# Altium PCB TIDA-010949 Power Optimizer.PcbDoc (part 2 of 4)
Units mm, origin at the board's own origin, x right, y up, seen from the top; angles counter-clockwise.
Board outline 129.4 x 84 mm, 4 copper layers (Power1, Ground1, Ground2, Power2), stack 1.926 mm thick; 265 components, 128 nets, 802 pads, 1069 vias.
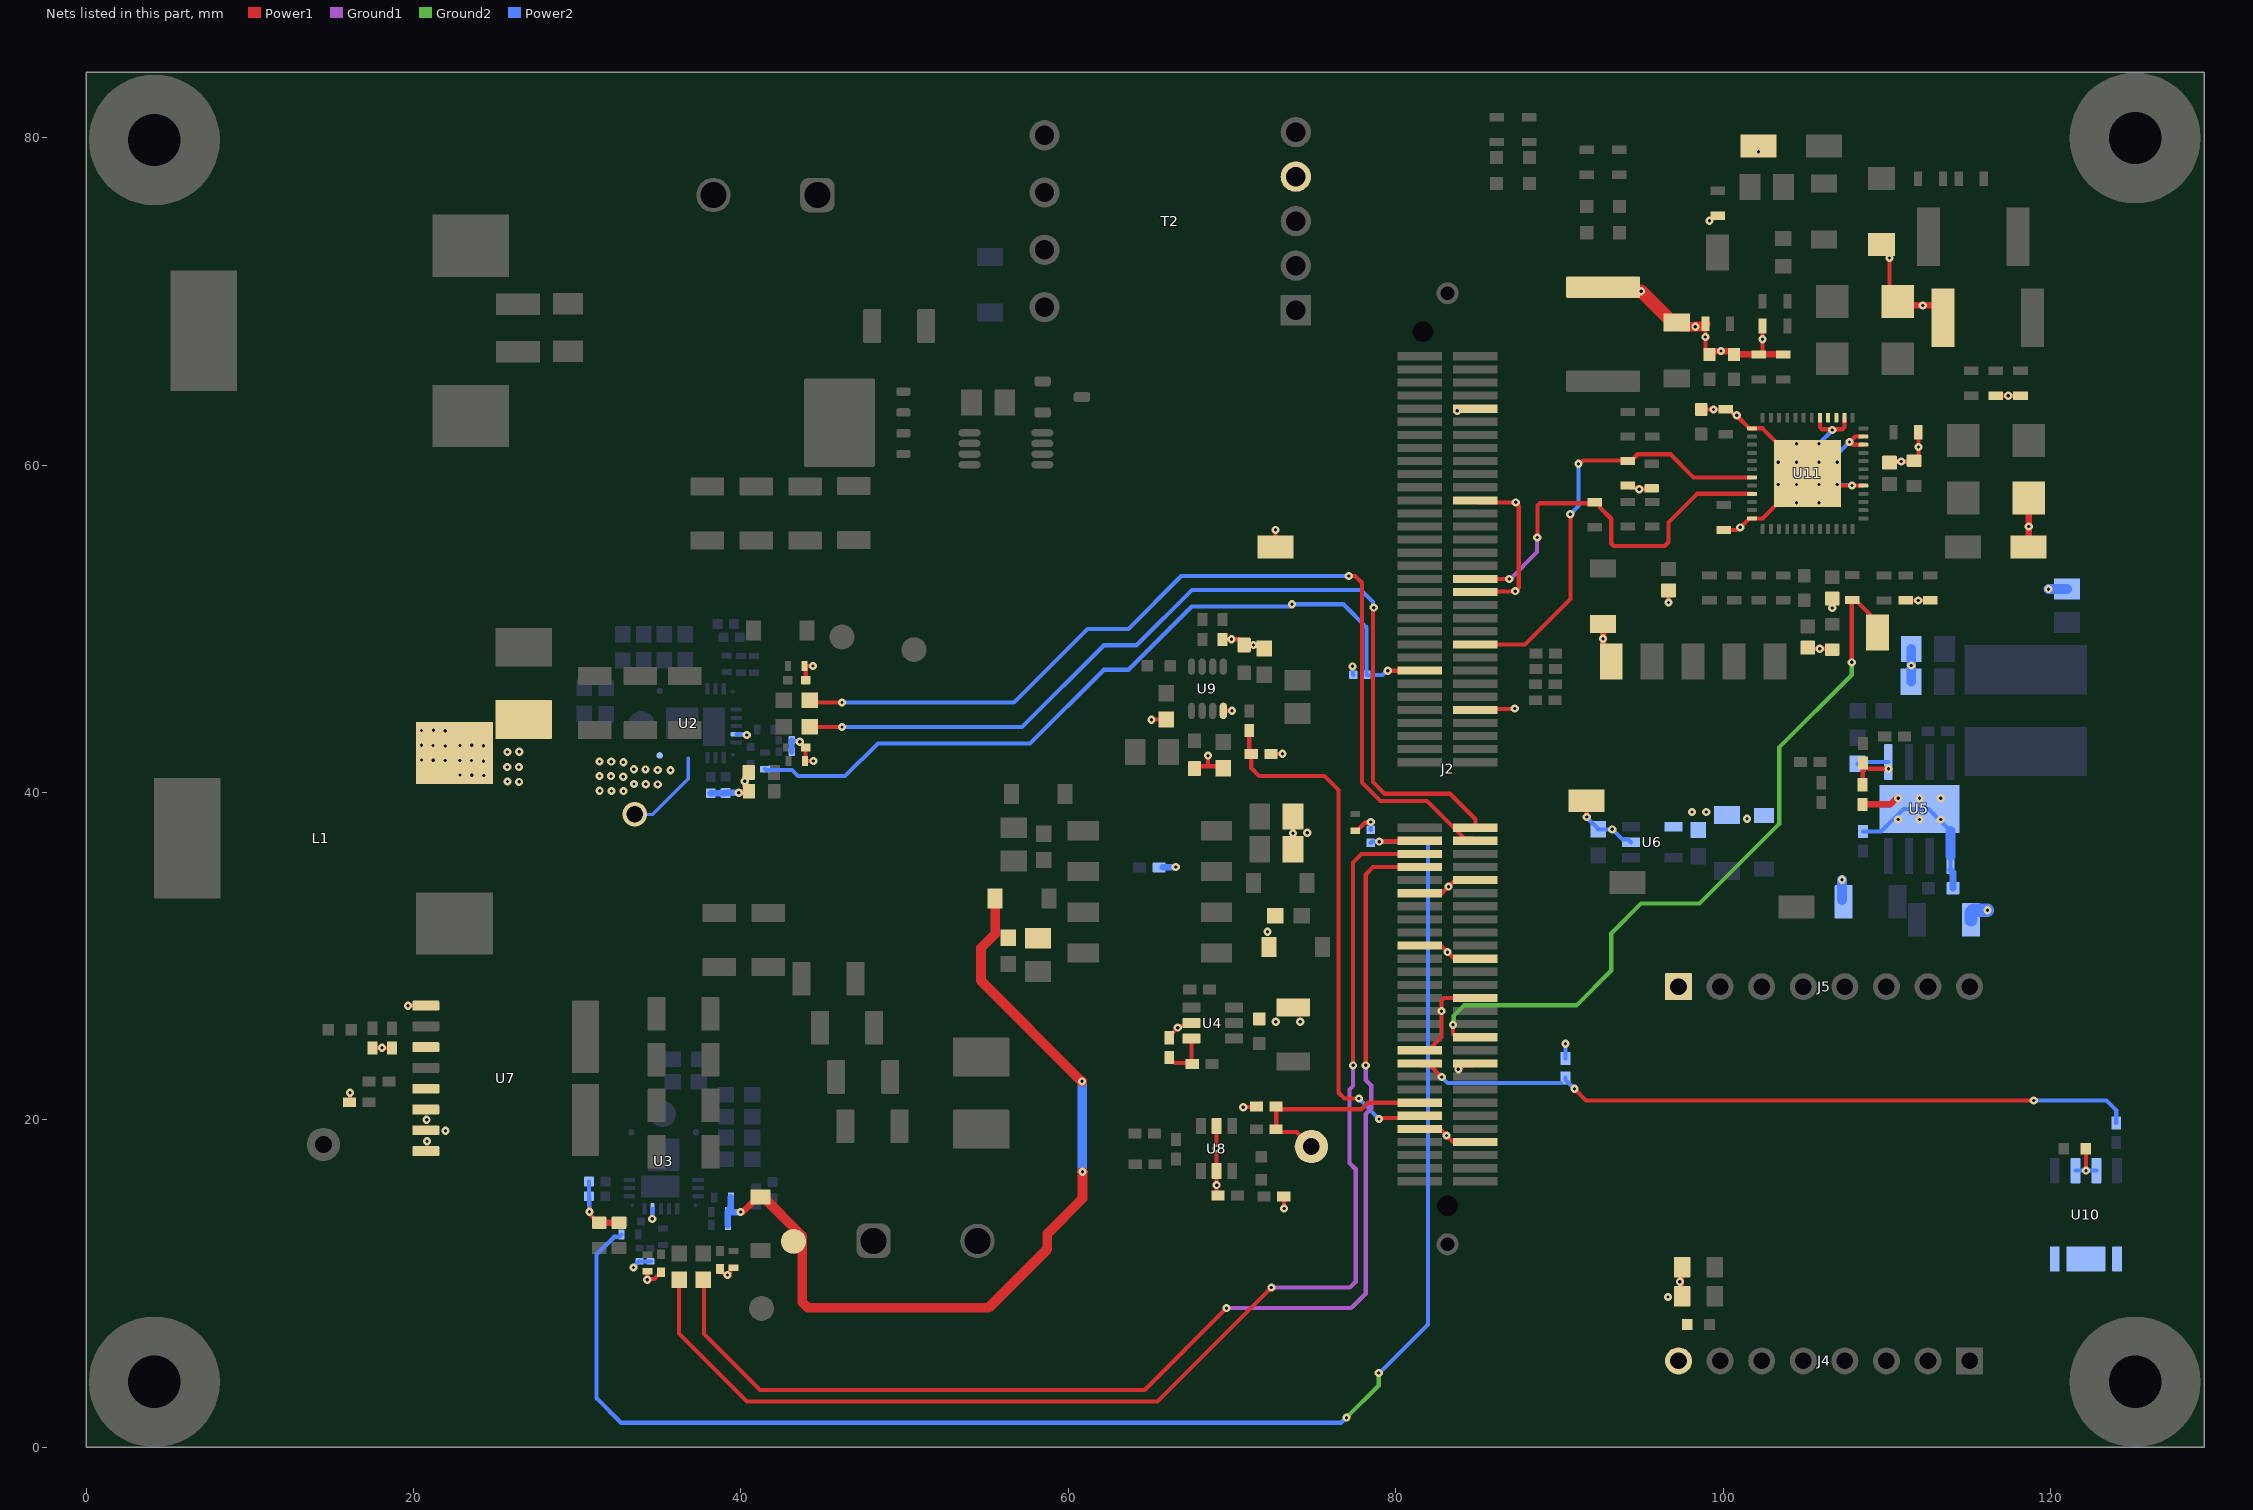
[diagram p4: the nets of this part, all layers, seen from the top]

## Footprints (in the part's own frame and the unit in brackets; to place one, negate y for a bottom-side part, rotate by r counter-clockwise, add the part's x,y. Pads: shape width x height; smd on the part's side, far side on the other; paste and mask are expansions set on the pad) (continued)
Wurth_750510476 [mm] "Wurth"
  rect 1.85x1.85 hole 1.181: 1(-8.175,5.44)
  round 1.85 hole 1.181: 2(-8.175,2.72) 3(-8.175,0) 4(-8.175,-2.72) 5(-8.175,-5.44) 6(7.175,-5.25) 7(7.175,-1.75) 8(7.175,1.75) 9(7.175,5.25)
  silkscreen extent -10.4,-6.9 9.9,6.9, body extent -9.88,-6.86 9.88,6.86, height 10.16

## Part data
C1: library part CMP-0007679-2, "CAP, CERM, 2.2 uF, 16 V, +/- 10%, X5R, 0805", Cap_Case=0805, Manufacturer=AVX, Supplier Part Number 1=478-2580-1-ND, TempCo=X5R, Tolerance_%=10%, Value1="0.009 ohm", Value2=16V, ValueDisplayed=2.2uF
C2 C3 C4 C21 C22 C23 C24 C25 C26 C27 C28 C29: library part CMP-0077894-3, "CAP, CERM, 0.22 µF, 100 V,+/- 10%, X7S, AEC-Q200 Grade 1, 0603", Cap_Case=0603, Manufacturer="Taiyo Yuden", Supplier Part Number 1=587-5012-1-ND, TempCo=X7S, Tolerance_%=10%, Value2=100V, ValueDisplayed=0.22µF
C5 C6 C7 C8 C9 C10 C11 C12 C13 C14 C15 C16 C17 C18 C19 C20 C47 C55 C56 C60 C61: library part CMP-0087970-1, "10µF ±10% 100V Ceramic Capacitor X7S 1210 (3225 Metric)", Manufacturer=Murata, TempCo=22%, Tolerance_%=0.1, ValueDisplayed=10uF
C30 C31 C65 C67: library part CMP-0006659-2, "CAP, CERM, 0.1 uF, 25 V, +/- 10%, X7R, 0402", Cap_Case=0402, Manufacturer=MuRata, Supplier Part Number 1=490-10698-1-ND, TempCo=X7R, Tolerance_%=10%, Value1=Unknown, Value2=25V, ValueDisplayed=0.1uF
C32 C33 C34 C35: library part CMP-0097874-1, "10 pF ±1% 50V Ceramic Capacitor C0G, NP0 0402 (1005 Metric)", Digikey Part Number=478-5717-1-ND, Manufacturer="KYOCERA AVX", Mouser Part Number=581-04025U100FAT2A, Operating Temperature Range="-55°C to +125°C", TempCo=30ppm/°C, Temperature Characteristic=C0G, Tolerance_%=1%, ValueDisplayed=10pF
C36 C37 C40 C41: library part CMP-0089452-2, "2.2µF ±10% 16V Ceramic Capacitor X7S 0603 (1608 Metric)", Digikey Part Number=490-12731-1-ND, Manufacturer=Murata, Mouser Part Number=81-GRM188C71C225KE1D, Operating Temperature Range="-55°C to +125°C", TempCo=22%, Temperature Characteristic=X7S, Tolerance_%=10%, ValueDisplayed=2.2uF
C38 C42: library part CMP-0096845-1, "Multi-Layer Ceramic Capacitor 100pF 25V C0G ±5% 0402 Paper T/R", Manufacturer=Murata, Operating Temperature Range="-55°C to +125°C", TempCo=30ppm/°C, Temperature Characteristic=C0G, Tolerance_%=5%, ValueDisplayed=100pF
C39 C43: library part CMP-0096975-1, "Multi-Layer Ceramic Capacitor 1uF 25V X5R ±10% 0402 Paper T/R", Manufacturer=Murata, Operating Temperature Range="-55°C to +85°C", TempCo=0.15, Temperature Characteristic=X5R, Tolerance_%=10%, ValueDisplayed=1uF
C44 C45 C50 C51 C113 C114 C115: library part CMP-0007677-2, "CAP, CERM, 10 uF, 16 V, +/- 10%, X5R, 0805", Cap_Case=0805, Manufacturer=AVX, Supplier Part Number 1=478-5165-1-ND, TempCo=X5R, Tolerance_%=10%, Value1=Unknown, Value2=16V, ValueDisplayed=10uF
C46: library part CMP-0006201-2, "CAP, CERM, 0.1 uF, 16 V, +/- 10%, X7R, 0402", Cap_Case=0402, Manufacturer=AVX, Supplier Part Number 1=478-7888-1-ND, TempCo=X7R, Tolerance_%=10%, Value1=Unknown, Value2=16V, ValueDisplayed=0.1uF
C48 C96 C97 C104 C111: library part CMP-0094779-1, "Cap Ceramic 100nF 100V X7R 10% SMD 0603 125°C Paper T/R", Digikey Part Number=478-06031C104K4T2ACT-ND, Manufacturer="KYOCERA AVX", Mouser Part Number=581-06031C104K4T2A, Operating Temperature Range="-55°C to +125°C", TempCo=15%, Temperature Characteristic=X7R, Tolerance_%=10%, ValueDisplayed=100nF
C49: library part CMP-0007254-4, "CAP, CERM, 200 pF, 100 V, +/- 5%, C0G/NP0, 0603", Cap_Case=0603, Manufacturer=MuRata, Supplier Part Number 1=490-1358-1-ND, TempCo=C0G/NP0, Tolerance_%=5%, Value1=Unknown, Value2=100V, ValueDisplayed=200pF
C52: library part CMP-0007475-4, "CAP, CERM, 2200 pF, 100 V, +/- 10%, X7R, 0603", Cap_Case=0603, Manufacturer=MuRata, Supplier Part Number 1=490-1478-1-ND, TempCo=X7R, Tolerance_%=10%, Value1=Unknown, Value2=100V, ValueDisplayed=2200pF
C53: library part CMP-0006683-2, "CAP, CERM, 2200 pF, 50 V, +/- 10%, X7R, 0402", Cap_Case=0402, Manufacturer=MuRata, Supplier Part Number 1=490-1305-1-ND, TempCo=X7R, Tolerance_%=10%, Value1=Unknown, Value2=50V, ValueDisplayed=2200pF
C54 C77: library part CMP-0006752-5, "CAP, CERM, 0.1 uF, 25 V, +/- 5%, X7R, 0603", Cap_Case=0603, Manufacturer=AVX, Supplier Part Number 1=478-3713-1-ND, TempCo=X7R, Tolerance_%=5%, Value1="0.05 ohm", Value2=25V, ValueDisplayed=0.1uF
C57 C58: library part CMP-0121608-1, "10 µF ±10% 16V Ceramic Capacitor X7R 0805 (2012 Metric)", Digikey Part Number=478-0805YC106KAT2ACT-ND, Manufacturer="Kyocera AVX", Mouser Part Number=581-0805YC106KAT2A, Operating Temperature Range="-55°C to +125°C", TempCo=15%, Temperature Characteristic=X7R, Tolerance_%=10%, ValueDisplayed=10uF
C59 C107: library part CMP-0090409-1, "0.1µF ±10% 16V Ceramic Capacitor X7R 0603 (1608 Metric)", Digikey Part Number=490-5796-1-ND, Manufacturer="Murata Electronics North America", Mouser Part Number=81-GCJ188R71C104KA1D, Operating Temperature Range="-55°C to +125°C", TempCo=15%, Temperature Characteristic=X7R, Tolerance_%=10%, ValueDisplayed=0.1uF
C62 C64: library part CMP-0006831-4, "CAP CER 1UF 16V Y5V 0603", Cap_Case=0603, Manufacturer=Yageo, PartNumber=CC0603MRY5V7BB105, Supplier Part Number 1=311-3414-1-ND, TempCo=X7R, Tolerance_%=10%, Value1=Unknown, Value2=16V, ValueDisplayed=1uF
C63: library part CMP-0008965-2, "CAP, CERM, 10 uF, 25 V, +/- 10%, X7R, 1206", Cap_Case=2220, Manufacturer=MuRata, Supplier Part Number 1=81-GRM31CR71E106KA12, TempCo=X7R, Tolerance_%=10%, Value1=Unknown, Value2=25V, ValueDisplayed=10uF
C66 C68: library part CMP-0078625-1, "CAP, CERM, 1 µF, 25 V,+/- 20%, X5R, 0402", Cap_Case=0402, Manufacturer=MuRata, Supplier Part Number 1=490-10018-1-ND, TempCo=X5R, Tolerance_%=20%, Value2=25V, ValueDisplayed=1µF
C69: library part CMP-0008996-2, "CAP, CERM, 0.39 uF, 100 V, +/- 10%, X7R, 1206", Cap_Case=1206, Manufacturer=MuRata, PartNumber=GRM31MR71H394KA01L, Supplier Part Number 1=490-1780-1-ND, TempCo=X7R, Tolerance_%=10%, Value1=Unknown, Value2=50V, ValueDisplayed=0.39uF
C70 C72: library part CMP-0006389-2, "CAP, CERM, 470 pF, 25 V, +/- 5%, C0G/NP0, 0402", Cap_Case=0402, Manufacturer=MuRata, Supplier Part Number 1=GRM1555C1E471JA01D-ND, TempCo=C0G/NP0, Tolerance_%=5%, Value1=Unknown, Value2=25V, ValueDisplayed=470pF
C71: library part CMP-0006658-2, "CAP, CERM, 0.01 uF, 25 V, +/- 10%, X7R, 0402", Cap_Case=0402, Manufacturer=MuRata, Supplier Part Number 1=490-1312-1-ND, TempCo=X7R, Tolerance_%=10%, Value1=Unknown, Value2=25V, ValueDisplayed=0.01uF
C73 C75: library part CMP-0860530-1, "CAP, CERM, 1000 pF, 25 V,+/- 5%, C0G/NP0, 0603", Cap_Case=0603, Manufacturer=Yageo, TempCo=C0G/NP0, Tolerance_%=5%, Value2=25V, ValueDisplayed=1000pF
C74 C76: library part CMP-0006453-2, "CAP, CERM, 300 pF, 50 V, +/- 5%, C0G/NP0, 0402", Cap_Case=0402, Manufacturer=MuRata, Supplier Part Number 1=490-3234-1-ND, TempCo=C0G/NP0, Tolerance_%=5%, Value1=Unknown, Value2=50V, ValueDisplayed=300pF
C78 C79: library part CMP-0006608-2, "CAP, CERM, 1 uF, 25 V, +/- 10%, X5R, 0402", Cap_Case=0402, Manufacturer=MuRata, Supplier Part Number 1=490-10017-1-ND, TempCo=X5R, Tolerance_%=10%, Value1=Unknown, Value2=25V, ValueDisplayed=1uF
C80 C83 C93 C95: library part CMP-0045719-1, "1000 pF ±10% 50V Ceramic Capacitor X7R 0603 (1608 Metric)", Digikey Part Number=399-C0603X102K5RAC7867CT-ND, Manufacturer=KEMET, Mouser Part Number=80-C0603X102K5R, Operating Temperature Range="-55°C to +125°C", TempCo=15%, Temperature Characteristic=X7R, Tolerance_%=10%, ValueDisplayed=1000pF
C81 C101 C106: library part CMP-0009015-2, "CAP, CERM, 10 uF, 50 V, +/- 10%, X5R, AEC-Q200 Grade 1, 1206", Cap_Case=1206, Manufacturer=MuRata, Supplier Part Number 1=490-12456-1-ND, TempCo=X5R, Tolerance_%=10%, Value1=Unknown, Value2=50V, ValueDisplayed=10uF
C82: library part CMP-0089171-1, "3300pF ±5% 100V Ceramic Capacitor X7R 0603 (1608 Metric)", Digikey Part Number=478-7420-1-ND, Manufacturer="AVX Corporation", Mouser Part Number=581-06031C332J4Z2A, Operating Temperature Range="-55°C to +125°C", TempCo=15%, Temperature Characteristic=X7R, Tolerance_%=5%, ValueDisplayed=3300pF
C84: library part CMP-0008779-2, "CAP, CERM, 1 uF, 100 V, +/- 10%, X7R, AEC-Q200 Grade 1, 1206", Cap_Case=1206_180, Manufacturer=TDK, Supplier Part Number 1=445-5845-1-ND, TempCo=X7R, Tolerance_%=10%, Value1="0.004575 ohm", Value2=100V, ValueDisplayed=1uF
C85: library part CMP-0007433-4, "CAP, CERM, 0.01 uF, 50 V, +/- 10%, X7R, 0603", Cap_Case=0603, Manufacturer=MuRata, Supplier Part Number 1=490-1512-1-ND, TempCo=X7R, Tolerance_%=10%, Value1=Unknown, Value2=50V, ValueDisplayed=0.01uF
C86 C99 C100 C102 C103 C105: library part CMP-0750039-1, "CAP, CERM, 0.01 µF, 50 V,+/- 10%, X7R, 0603", Cap_Case=0603, Manufacturer="Wurth Elektronik", TempCo=X7R, Tolerance_%=10%, Value2=50V, ValueDisplayed=0.01µF
C87: library part CMP-0007192-4, "CAP, CERM, 1800 pF, 50 V, +/- 5%, C0G/NP0, 0603", Cap_Case=0603, Manufacturer=MuRata, Supplier Part Number 1=490-1457-1-ND, TempCo=C0G/NP0, Tolerance_%=5%, Value1=Unknown, Value2=50V, ValueDisplayed=1800pF
C88: library part CMP-0006764-4, "CAP, CERM, 1000 pF, 50 V, +/- 10%, C0G/NP0, 0603", Cap_Case=0603, Manufacturer=AVX, Supplier Part Number 1=478-3718-1-ND, TempCo=C0G/NP0, Tolerance_%=10%, Value1="0.048 ohm", Value2=50V, ValueDisplayed=1000pF
C89: library part CMP-0007164-4, "CAP, CERM, 560 pF, 25 V, +/- 5%, C0G/NP0, 0603", Cap_Case=0603, Manufacturer=MuRata, Supplier Part Number 1=GRM1885C1E561JA01D-ND, TempCo=C0G/NP0, Tolerance_%=5%, Value1=Unknown, Value2=25V, ValueDisplayed=560pF
C90: library part CMP-0007203-4, "CAP, CERM, 270 pF, 50 V, +/- 5%, C0G/NP0, 0603", Cap_Case=0603, Manufacturer=MuRata, Supplier Part Number 1=490-1437-1-ND, TempCo=C0G/NP0, Tolerance_%=5%, Value1=Unknown, Value2=50V, ValueDisplayed=270pF
C91: library part CMP-0006729-4, "CAP, CERM, 1200 pF, 100 V, +/- 5%, X7R, 0603", Cap_Case=0603, Manufacturer=AVX, Supplier Part Number 1=478-3702-1-ND, TempCo=X7R, Tolerance_%=5%, Value1="0.254 ohm", Value2=100V, ValueDisplayed=1200pF
C92 C94: library part CMP-0122291-1, "1 µF ±10% 50V Ceramic Capacitor X7T 0603 (1608 Metric)", Digikey Part Number=490-GCM188D71H105KE36JCT-ND, Manufacturer=Murata, Mouser Part Number=81-GCM188D71H105KE6J, Operating Temperature Range="-55°C to +125°C", TempCo=+22/-33%, Temperature Characteristic=X7T, Tolerance_%=10%, ValueDisplayed=1uF
C98: library part CMP-0093976-1, "Cap Ceramic 47uF 25V X7R 20% Pad SMD 2220 +125°C Automotive T/R", Manufacturer=TDK, Operating Temperature Range="-55°C to +125°C", TempCo=0.15, Temperature Characteristic=X7R, Tolerance_%=0.2%, ValueDisplayed=47uF
C108: library part CMP-0006561-2, "CAP, CERM, 0.01 uF, 10 V, +/- 10%, X5R, 0402", Cap_Case=0402, Manufacturer=MuRata, Supplier Part Number 1=GRM155R61A103KA01D-ND, TempCo=X5R, Tolerance_%=10%, Value1=Unknown, Value2=10V, ValueDisplayed=0.01uF
C109 C110: library part CMP-0098338-1, "100 pF ±5% 16V Ceramic Capacitor C0G, NP0 0402 (1005 Metric)", Digikey Part Number=399-C0402C101J4GAC7867CT-ND, Manufacturer=KEMET, Mouser Part Number=80-C0402C101J4G, Operating Temperature Range="-55°C to +125°C", TempCo=30ppm/°C, Temperature Characteristic=C0G, Tolerance_%=5%, ValueDisplayed=100pF
C112: library part CMP-0006640-2, "CAP, CERM, 0.1 uF, 16 V, +/- 5%, X7R, 0402", Cap_Case=0402, Manufacturer=MuRata, Supplier Part Number 1=490-6327-1-ND, TempCo=X7R, Tolerance_%=5%, Value1=Unknown, Value2=16V, ValueDisplayed=0.1uF
D1 D4 D5: library part CMP-0028543-2, "Diode, Schottky, 40 V, 0.35 A, SOD-123", Manufacturer="Diodes Inc.", Value1=0.35A, Value2=0.55V
D2 D3 D6: library part CMP-0077599-3, "Diode, Zener, 5.1 V, 500 mW, SOD-123", Manufacturer=Vishay-Semiconductor, Power_W=500mW, Value1=0.5W
D7 D15: library part CMP-0002946-3, "LED, Blue, SMD", Color=Blue, Manufacturer="Wurth Elektronik", Power_TotalModule=105mW, Value1=0.105W, Value2=3.2V
D8: library part CMP-0005782-1, "Diode, Zener, 3.6 V, 500 mW, SOD-123", Manufacturer="ON Semiconductor", PartNumber=MMSZ4685T1G, Power_W=500mW, Supplier Part Number 1=MMSZ4685T1GOSCT-ND, Value1=0.5W
D9 D11 D13 D14: library part CMP-0028416-2, "Diode, Schottky, 50 V, 3 A, SMA", Manufacturer="Diodes Inc.", Value1=3A, Value2=0.7V
D10: library part CMP-0085011-1, "Diode, TVS, Bi, 22 V, 35.5 Vc, 400 W, 11.3 A, SMA (non-polarized)", Manufacturer=Littelfuse, Value1=35.5V
D12 D16: library part CMP-0002947-3, "LED, Red, SMD", Color=Red, Manufacturer="Wurth Elektronik", Power_TotalModule=72mW, Value1=0.072W, Value2=2V
FB1 FB2 FB3: library part CMP-0037505-1, "600 Ohms @ 100 MHz 1 Power, Signal Line Ferrite Bead 0603 (1608 Metric) 1A 200mOhm", Digikey Part Number=MH1608-601YCT-ND, Impedance At Frequency="600Ω @ 100MHz", Manufacturer=Bourns, Mouser Part Number=652-MH1608-601Y, Operating Temperature Range="-55°C to +125°C", Test Frequency=100MHz, Tolerance_%=25%
H1 H2 H3 H4: library part CMP-0003617-1, "Machine Screw, Round, #4-40 x 1/4, Nylon, Philips panhead", Manufacturer="B&F Fastener Supply", Supplier Part Number 1=H542-ND
H5 H6 H7 H8: library part CMP-0003610-1, "Standoff, Hex, 0.5\"L #4-40 Nylon", Manufacturer=Keystone, Supplier Part Number 1=36-1902C-ND
J1 J3: library part CMP-0075360-1, "Terminal Block, 6.35mm, 2x1, TH", Color=Green, Current_A=30A, Manufacturer="On-Shore Technology", Supplier Part Number 1=ED2675-ND, Voltage_V=300V
J2: library part CMP-0003814-2, "C2000 controlCARD-120HSEC connector, SMT", Manufacturer=Samtec
J4 J5: library part CMP-0075419-2, "Header, 100mil, 8x1, Gold, TH", Color=Black, Current_A=6.3A, Manufacturer=Samtec, Supplier Part Number 1=SAM1029-08-ND, Voltage_V=550V
L1 L4: library part CMP-0060824-1, "Inductor, Shielded E Core, Ferrite, 3.6 uH, 25 A, 0.0017 ohm, SMD", Manufacturer=Coilcraft, Value1="0.0017 ohm", Value2=25A, ValueDisplayed=3.6uH
L2: library part CMP-0102060-1, "WE-PD2SA SMT Power Inductor, size 7850, 68uH, 1.12A, 290mOhm", Case/Size Code=7850, DC Resistance=246mOhm, DC Resistance Max=290mOhm, Inductance=68uH, Manufacturer="Wurth Elektronik", Operating Temperature Max=150°C, Operating Temperature Min=-50°C, Rated Current=1.12A, Saturation Current=1A, Self Resonant Frequency=7.5MHz
L3: library part CMP-0058657-1, "Inductor, Wirewound, Ferrite, 1 uH, 0.595 A, 0.25 ohm, SMD", Manufacturer=MuRata, Value1="0.25 ohm", Value2=0.595A, ValueDisplayed=1uH
L5: library part CMP-0061680-2, "Inductor, Drum Core, Ferrite, 1 mH, 0.1 A, 19 ohm, SMD", Manufacturer=Coilcraft, Value1="19 ohm", Value2=0.1A, ValueDisplayed=1mH
L6: library part CMP-0061972-2, "Inductor, Drum Core, Ferrite, 1.5 mH, 0.08 A, 21 ohm, SMD", Manufacturer=Coilcraft, Value1="21 ohm", Value2=0.08A, ValueDisplayed=1.5mH
LBL1: library part CMP-0003625-1, "Thermal Transfer Printable Labels, 0.650\" W x 0.200\" H - 10,000 per roll", Manufacturer=Brady, Supplier Part Number 1=97C5133
Logo1: library part CMP-0074838-1, "Texas Instrument Corporate Signature"
Logo2: library part CMP-0074844-1
Logo3: library part CMP-0074847-1, "FCC_disclaimer"
Logo4: library part CMP-0074769-1
Q1: library part CMP-0000958-3, "MOSFET, N-CH, 100 V, 17 A, DNK0008A (VSON-CLIP-8)", Alternate Manufacturer=None, Manufacturer="Texas Instruments", Supplier Part Number 1=296-37478-6-ND, Value2="48 nC"
Q2: library part CMP-0000949-3, "MOSFET, N-CH, Depletion Mode, 100 V, 0.17 A, AEC-Q101, SOT-23", Alternate Manufacturer=None, Manufacturer="Infineon Technologies", Supplier Part Number 1="BSS169 H6327-ND", Value2="2.1 nC"
R1: library part CMP-0094948-1, "0 Ohms Jumper 0.1W, 1/10W Chip Resistor 0402 (1005 Metric) - Thick Film", Digikey Part Number=2679-CR0402-10W-000TTR-ND, Manufacturer=Venkel, Operating Temperature Range="-55°C to +155°C", Power_W=100mW
R2 R6: library part CMP-0042666-1, "Res Metal Strip 2512 0.001 Ohm 1% 3W ±50ppm/C Pad SMD Automotive T/R", Manufacturer="TT Electronics", Mouser Part Number=66-ULRG3R001FLFSLT, Operating Temperature Range=to, Power_W=3W, TempCo=50ppm/°C, Tolerance_%=1%
R3 R4 R5 R7: library part CMP-0026262-2, "RES, 2.00, 1%, 0.063 W, AEC-Q200 Grade 0, 0402", Manufacturer=Vishay-Dale, Power_W=63mW, Supplier Part Number 1=541-2.00LLCT-ND, TempCo="100 ppm/C", Tolerance_%=1%, Value2=0.063W, Value_Code=2R00, ValueDisplayed=2.00
R8 R9 R14 R15: library part CMP-0078781-1, "RES, 10.5 k, 1%, 0.063 W, 0402", Manufacturer="Yageo America", Power_W=63mW, Supplier Part Number 1=YAG2951CT-ND, TempCo="100 ppm/C", Tolerance_%=1%, Value2=0.063W, Value_Code=10k5, ValueDisplayed=10.5k
R10 R11 R12 R13: library part CMP-0022908-4, "RES, 20.0, 1%, 0.1 W, 0603", Manufacturer=Yageo, Power_W=100mW, Supplier Part Number 1=311-20.0HRCT-ND, TempCo="100 ppm/C", Tolerance_%=1%, Value2=0.1W, Value_Code=20R0, ValueDisplayed=20.0
R16 R17 R58: library part CMP-0022895-5, "RES, 1.00 k, 1%, 0.1 W, 0603", Manufacturer=Yageo, Power_W=100mW, Supplier Part Number 1=311-1.00KHRCT-ND, TempCo="100 ppm/C", Tolerance_%=1%, Value2=0.1W, Value_Code=1k00, ValueDisplayed=1.00k
R18: library part CMP-0026325-2, "RES, 392 k, 1%, 0.063 W, AEC-Q200 Grade 0, 0402", Manufacturer=Vishay-Dale, Power_W=63mW, Supplier Part Number 1=541-392KLCT-ND, TempCo="100 ppm/C", Tolerance_%=1%, Value2=0.063W, Value_Code=392k
R19 R24 R26 R27 R28 R73 R75: library part CMP-0026936-3, "RES, 47, 5%, 0.063 W, AEC-Q200 Grade 0, 0402", Manufacturer=Vishay-Dale, Power_W=63mW, Supplier Part Number 1=541-47JCT-ND, TempCo="200 ppm/C", Tolerance_%=5%, Value2=0.063W, Value_Code=47R0, ValueDisplayed=47
R20: library part CMP-0026457-2, "RES, 57.6 k, 1%, 0.063 W, AEC-Q200 Grade 0, 0402", Manufacturer=Vishay-Dale, Power_W=63mW, Supplier Part Number 1=541-57.6KLCT-ND, TempCo="100 ppm/C", Tolerance_%=1%, Value2=0.063W, Value_Code=57k6, ValueDisplayed=57.6k
R21: library part CMP-0025971-3, "RES, 115 k, 1%, 0.063 W, AEC-Q200 Grade 0, 0402", Manufacturer=Vishay-Dale, Power_W=63mW, Supplier Part Number 1=541-115KLCT-ND, TempCo="100 ppm/C", Tolerance_%=1%, Value2=0.063W, Value_Code=115k
R22: library part CMP-0026825-5, "RES, 10 k, 5%, 0.063 W, AEC-Q200 Grade 0, 0402", Manufacturer=Vishay-Dale, Power_W=63mW, Supplier Part Number 1=541-10KJCT-ND, TempCo="200 ppm/C", Tolerance_%=5%, Value2=0.063W, Value_Code=10k0, ValueDisplayed=10k
R23: library part CMP-0083579-1, "RES, 5.6, 5%, 0.5 W, 1210", Manufacturer=Yageo, Power_W=500mW, TempCo="200 ppm/C", Tolerance_%=5%, Value2=0.5W, Value_Code=5R60, ValueDisplayed=5.6
R25: library part CMP-0025958-3, "RES, 10.0 k, 1%, 0.063 W, AEC-Q200 Grade 0, 0402", Manufacturer=Vishay-Dale, Power_W=63mW, Supplier Part Number 1=541-10.0KLCT-ND, TempCo="100 ppm/C", Tolerance_%=1%, Value2=0.063W, Value_Code=10k0, ValueDisplayed=10.0k
R29 R61 R62 R76: library part CMP-0025936-5, "RES, 680, 5%, 0.1 W, 0603", Manufacturer=Yageo, Power_W=100mW, Supplier Part Number 1=311-680GRCT-ND, TempCo="100 ppm/C", Tolerance_%=5%, Value2=0.1W, Value_Code=680R, ValueDisplayed=680
R30 R38: library part CMP-0025923-5, "RES, 43 k, 5%, 0.1 W, 0603", Manufacturer=Yageo, Power_W=100mW, Supplier Part Number 1=311-43KGRCT-ND, TempCo="100 ppm/C", Tolerance_%=5%, Value2=0.1W, Value_Code=43k0, ValueDisplayed=43k
R31 R32 R63: library part CMP-0026751-1, "RES, 47.0, 1%, 0.063 W, 0402", Manufacturer="KOA Speer", Power_W=63mW, Supplier Part Number 1=660-RK73H1ETTP47R0F, TempCo="100 ppm/C", Tolerance_%=1%, Value2=0.063W, Value_Code=47R0, ValueDisplayed=47.0
R33: library part CMP-0026486-2, "RES, 60.4 k, 1%, 0.063 W, AEC-Q200 Grade 0, 0402", Manufacturer=Vishay-Dale, Power_W=63mW, Supplier Part Number 1=541-60.4KLCT-ND, TempCo="100 ppm/C", Tolerance_%=1%, Value2=0.063W, Value_Code=60k4, ValueDisplayed=60.4k
R34 R37: library part CMP-0026749-1, "RES, 10.0, 1%, 0.063 W, 0402", Manufacturer="KOA Speer", Power_W=63mW, Supplier Part Number 1=660-RK73H1ETTP10R0F, TempCo="100 ppm/C", Tolerance_%=1%, Value2=0.063W, Value_Code=10R0, ValueDisplayed=10.0
R35: library part CMP-0025993-3, "RES, 12.7 k, 1%, 0.063 W, AEC-Q200 Grade 0, 0402", Manufacturer=Vishay-Dale, Power_W=63mW, Supplier Part Number 1=541-12.7KLCT-ND, TempCo="100 ppm/C", Tolerance_%=1%, Value2=0.063W, Value_Code=12k7, ValueDisplayed=12.7k
R39 R51: library part CMP-0025928-5, "RES, 510, 5%, 0.1 W, 0603", Manufacturer=Yageo, Power_W=100mW, Supplier Part Number 1=311-510GRCT-ND, TempCo="100 ppm/C", Tolerance_%=5%, Value2=0.1W, Value_Code=510R, ValueDisplayed=510
R40 R41: library part CMP-0019234-2, "RES, 30.1 k, 0.5%, 0.1 W, 0805", Manufacturer="Susumu Co Ltd", Power_W=100mW, Supplier Part Number 1=RR12P30.1KDCT-ND, TempCo="25 ppm/C", Tolerance_%=0.5%, Value2=0.1W, Value_Code=30k1, ValueDisplayed=30.1k
R42 R44: library part CMP-0026454-2, "RES, 56.2, 1%, 0.063 W, AEC-Q200 Grade 0, 0402", Manufacturer=Vishay-Dale, Power_W=63mW, Supplier Part Number 1=541-56.2LCT-ND, TempCo="100 ppm/C", Tolerance_%=1%, Value2=0.063W, Value_Code=56R2, ValueDisplayed=56.2
R43 R45: library part CMP-0088560-2, "High Precision-High Stability Chip Resistor Thin Film 0603 1kOhm 0.1% Paper T/R", Digikey Part Number=YAG1237CT-ND, Manufacturer=Yageo, Mouser Part Number=603-RT0603BRD071KL, Operating Temperature Range="-55°C to +155°C", Power_W=100mW, TempCo=25ppm/°C, Tolerance_%=0.1%
R46 R47 R48 R49 R53 R54 R60: library part CMP-0098286-1, "10 kOhms ±5% 0.1W, 1/10W Chip Resistor 0603 (1608 Metric) Thick Film", Digikey Part Number=541-CRCW060310K0JNEBCCT-ND, Manufacturer=Vishay, Mouser Part Number=71-CRCW060310K0JNEBC, Operating Temperature Range="-55°C to +155°C", Power_W=100mW, TempCo=200ppm/°C, Tolerance_%=5%
R50 R52: library part CMP-0022735-5, "RES, 100 k, 1%, 0.1 W, 0603", Manufacturer=Yageo, Power_W=100mW, Supplier Part Number 1=311-100KHRCT-ND, TempCo="100 ppm/C", Tolerance_%=1%, Value2=0.1W, Value_Code=100k
R55: library part CMP-0025913-5, "RES, 33 k, 5%, 0.1 W, 0603", Manufacturer=Yageo, Power_W=100mW, Supplier Part Number 1=311-33KGRCT-ND, TempCo="100 ppm/C", Tolerance_%=5%, Value2=0.1W, Value_Code=33k0, ValueDisplayed=33k
R56: library part CMP-0020737-3, "RES, 4.7, 5%, 0.125 W, AEC-Q200 Grade 0, 0805", Manufacturer=Panasonic, Power_W=125mW, Supplier Part Number 1=P4.7ACT-ND, TempCo="600 ppm/C", Tolerance_%=5%, Value2=0.125W, Value_Code=4R70, ValueDisplayed=4.7
R57: library part CMP-0025912-5, "RES, 330, 5%, 0.1 W, 0603", Manufacturer=Yageo, Power_W=100mW, Supplier Part Number 1=311-330GRCT-ND, TempCo="100 ppm/C", Tolerance_%=5%, Value2=0.1W, Value_Code=330R, ValueDisplayed=330
R59: library part CMP-0022986-5, "RES, 2.20 k, 1%, 0.1 W, 0603", Manufacturer=Yageo, Power_W=100mW, Supplier Part Number 1=311-2.20KHRCT-ND, TempCo="100 ppm/C", Tolerance_%=1%, Value2=0.1W, Value_Code=2k20, ValueDisplayed=2.20k
R64 R65 R66 R67 R68 R69 R70 R71: library part CMP-0031873-1, "0 Ohms Jumper Chip Resistor 0402 (1005 Metric) Anti-Sulfur, Current Sense, Flame Retardant Coating, Moisture Resistant, Safety Metal Foil", Digikey Part Number=4463-D1LPC0402CJUMPF-T10CT-ND, Manufacturer="Thin Film Technology", Max Current=20A, Operating Temperature Range="-55°C to +170°C"
R72 R74: library part CMP-0094624-1, "4.7 kOhms ±5% 0.1W, 1/10W Chip Resistor 0402 (1005 Metric) Automotive AEC-Q200 Thick Film", Digikey Part Number=10-ERJ-H2GJ472XCT-ND, Manufacturer=Panasonic, Mouser Part Number=667-ERJ-H2GJ472X, Operating Temperature Range="-55°C to +175°C", Power_W=100mW, TempCo=200ppm/°C, Tolerance_%=5%
T1: library part "EP7, 070-7148", "EP7 8-Term., SMT, Horizontal", Manufacturer="Würth Elektronik Midcom", Package=EP7
T2: library part CMP-0030703-1, "Transformer, 870uH. TH", Manufacturer="Wurth Elektronik", ValueDisplayed=870uH
TP1 TP13 TP14 TP15 TP18 TP19 TP20 TP21 TP22 TP23 TP24 TP25 TP26 TP27 TP28: library part CMP-0003968-1, "Test Point, SMT", Manufacturer=Harwin, Supplier Part Number 1=952-2664-1-ND
TP16 TP17: library part CMP-0055138-2, "Test Point, Miniature, Black, TH", Color=Black, Manufacturer="Keystone Electronics", Supplier Part Number 1=36-5001-ND
U1: library part CMP-0076397-2, "Zero Iq Reverse Polarity Protection Smart Diode Controller, DGK0008A (VSSOP-8)", Alternate Manufacturer="Texas Instruments"
U2 U3: library part CMP-0120692-1, "100-V, 53-A GaN Half-Bridge Power Stage", Manufacturer="Texas Instruments", Max Supply Voltage=5.25V, Min Supply Voltage=4.75V, Nominal Supply Current=12mA, Operating Temperature Range="-40°C to +125°C"
U4: library part CMP-0121876-1, "SIMPLE SWITCHER® Power Converter, 4-V to 42-V, 1-A Buck Converter, SOT23", Manufacturer="Texas Instruments", Max Supply Voltage=42V, Min Supply Voltage=4V, Nominal Supply Current=26.5-420uA, Operating Temperature Range="-40°C to +150°C", Output Voltage=0.8-28V, Switching Frequency=400kHz
U5: library part CMP-0089262-2, "Buck Switching Regulator IC Positive Adjustable 1.2V 1 Output 1A 8-PowerSOIC (0.154\", 3.90mm Width)", Digikey Part Number=296-LM5164DDARCT-ND, Manufacturer="Texas Instruments", Max Supply Voltage=100V, Min Supply Voltage=6V, Mouser Part Number=595-LM5164DDAR, Nominal Supply Current=600uA, Operating Temperature Range="-40°C to +150°C", Output Voltage=1.2-90V, Switching Frequency=1MHz
U6: library part CMP-0092532-1, "300-mA, Ultra-Low-Noise, Low-IQ, High PSRR LDO", Digikey Part Number=296-TPS7A2033PDBVRCT-ND, Dropout Voltage=145mV, Manufacturer="Texas Instruments", Max Supply Voltage=6V, Min Supply Voltage=1.6V, Mouser Part Number=595-TPS7A2033PDBVR, Nominal Supply Current=6.5uA, Operating Temperature Range="-40°C to +125°C", Output Voltage=3.3V
U7: library part CMP-0097970-1, Manufacturer="Texas Instruments", Operating Temperature Range=to
U8: library part CMP-0013234-2, "Bidirectional, Low- and High-Side Measurement, Multichannel, Voltage Output, Current-Sense Amplifier, DBV0006A (SOT-6)", Alternate Manufacturer="Texas Instruments"
U9: library part CMP-0086102-1, "TLV9002IDDFR, DDF0008A (SOT-23-THN-8)", Alternate Manufacturer="Texas Instruments"
U10: library part CMP-0122473-1, "Automotive ±1.5°C, 3-kVRMS Isolated Temperature Sensor With Analog Output With < 2 Seconds Response Time and 500VRMS Working Voltage", Manufacturer="Texas Instruments", Max Supply Voltage=5.5V, Min Supply Voltage=2.3V, Operating Supply Current=10uA, Operating Temperature Range="-40°C to +150°C"
U11: library part CMP-0040436-2, "Powerline Communications Analog Front End, 7 to 26 V, -40 to 125 degC, 48-pin QFN (RGZ48), Green (RoHS & no Sb/Br)", Manufacturer="Texas Instruments", Rating=Catalog, Total Supply Voltage(Max)(+5V is 5, +/-5V is 10)=26, Total Supply Voltage(Min)(+5V is 5, +/-5V is 10)=7

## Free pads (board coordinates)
  round 1.524 smd: 2(43.213,12.58) 3(41.267,8.486) 4(46.174,49.5) 5(50.58,48.73)

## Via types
v1: diameter 0.5, hole 0.2, Power1 to Power2, tented both sides, 1061 vias
v2: diameter 1.5/1.5/1.5/1.5 (per signal layer), hole 1, Power1 to Power2, 4 vias
v3: diameter 3.508, hole 3.1, Power1 to Power2, tented both sides, 4 vias

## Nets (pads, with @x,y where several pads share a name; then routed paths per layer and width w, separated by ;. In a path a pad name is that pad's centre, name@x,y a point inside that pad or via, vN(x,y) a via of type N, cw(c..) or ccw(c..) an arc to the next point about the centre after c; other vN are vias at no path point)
5V_FB: R20.1 R25.2 U4.3 | length 3.1
  Power1 w0.254: R25.2@66.174,23.818 66.174,23.718 66.347,23.545 66.447,23.545 66.524,23.468 67.524,23.468 U4.3@67.524,24.968
ADCIN: J2.23 R57.2 TP27.1 | length 46.6
  Power1 w0.254: v1(83.506,25.813) 83.506,25.267 83.723,25.05 J2.23@84.874,25.05 ; v1(107.864,47.953) 107.864,51.731 R57.2@107.9,51.767 108.091,51.767 TP27.1@109.674,50.184
  Ground2 w0.254: v1(83.506,25.813) 83.555,25.862 83.555,26.381 84.174,27 91.055,27 93.174,29.119 93.174,31.395 94.989,33.211 98.564,33.211 103.432,38.079 103.432,42.759 107.864,47.19 v1(107.864,47.953)
amb_tmp: U10.5 U10.6 U10.7
amb_tmp_mcu: C108.1 J2.20 R63.1 | length 44.5
  Power1 w0.254: J2.20@81.474,23.45 81.597,23.327 82.115,23.327 v1(82.814,22.627) ; v1@90.894,21.931 v1(90.924,21.902) 91.634,21.192 v1(118.982,21.192)
  Power2 w0.254: v1(82.814,22.627) 83.181,22.261 C108.1@90.084,22.261 ; C108.1@90.374,22.6 C108.1@90.374,22.55 90.374,22.45 90.922,21.902 v1(90.924,21.902) ; v1(118.982,21.192) 123.437,21.192 124.02,20.609 R63.1@124.02,19.811
BOOST_FLT: C109.2 J2.72 R73.1 | length 48.1
  Power1 w0.254: v1(79.514,47.443) 81.466,47.443 J2.72@81.474,47.45
  Power2 w0.254: R73.1@41.474,41.427 41.532,41.368 43.122,41.368 43.49,41 46.37,41 48.37,43 57.674,43 62.174,47.5 63.674,47.5 67.546,51.373 73.546,51.373 v1(73.674,51.5) 76.812,51.5 78.219,50.093 C109.2@78.219,47.188 79.191,47.188 79.446,47.443 v1(79.514,47.443)
BOOST_HI_PWM: J2.53 R10.1 | length 57.8
  Power1 w0.254: R10.1@44.215,45.635 44.35,45.5 v1(46.174,45.5) ; v1(77.136,53.229) 77.53,53.229 77.941,52.817 77.941,40.611 79.065,39.487 81.921,39.487 84.235,37.173 84.751,37.173 J2.53@84.874,37.05
  Power2 w0.254: v1(46.174,45.5) 56.674,45.5 61.174,50 63.674,50 66.902,53.229 v1(77.136,53.229)
BOOST_LO_PWM: J2.55 R12.1 | length 56.9
  Power1 w0.254: R12.1@44.215,44.01 44.225,44 v1(46.174,44) ; v1(78.662,51.295) 78.618,51.252 78.618,40.641 79.332,39.928 83.311,39.928 84.874,38.365 J2.55@84.874,37.85
  Power2 w0.254: v1(46.174,44) 57.174,44 62.174,49 64.174,49 67.551,52.377 77.868,52.377 78.614,51.631 78.614,51.342 v1(78.662,51.295)
BOOST_SW: L1.2 R6.2 U2.5 | length 5.5
  Power2 w0.2: v2(33.512,38.662) 34.621,38.662 36.793,40.834 36.793,42.11
  other v1: 32.823,40.086 31.371,40.111 32.09,40.094 34.194,40.508 34.927,40.5 33.475,40.524 25.736,40.667 26.455,40.651 32.816,40.963 32.072,41.001 31.359,41.006 23.558,41.05 24.291,41.041 22.839,41.066 34.919,41.376 35.697,41.359 33.463,41.42 34.175,41.415 26.437,41.557 25.724,41.562 32.823,41.85 32.079,41.888 31.366,41.893 24.284,41.918 21.947,41.961 22.827,41.961 23.54,41.956 20.495,41.985 21.214,41.969 25.734,42.476 26.457,42.486 21.94,42.837 20.483,42.881 21.196,42.876 22.837,42.875 24.281,42.861 23.56,42.885 20.493,43.794 21.937,43.78 21.216,43.804
BUCK_FLT: C110.2 J2.54 R75.1 | length 100.6
  Power1 w0.254: v1(79,37) 79.025,37.025 81.449,37.025 J2.54@81.474,37.05
  Ground2 w0.254: v1(76.997,1.812) 78.968,3.783 v1(78.968,4.539)
  Power2 w0.254: R75.1@32.712,12.999 32.575,12.862 32.268,12.862 31.174,11.768 31.174,3 32.674,1.5 76.666,1.5 v1@76.997,1.83 ; C110.2@78.476,36.918 78.557,37 v1(79,37) 81.83,37 81.979,36.851 81.979,7.502 79.017,4.539 v1(78.968,4.539)
BUCK_HI_PWM: J2.50 R11.1 | length 77
  Power1 w0.254: R11.1@37.7,10.239 37.756,10.183 37.756,6.917 41.174,3.5 64.674,3.5 v1(69.674,8.5) ; v1(78.176,23.331) 78.174,23.334 78.174,35 78.623,35.45 J2.50@81.474,35.45
  Ground1 w0.254: v1(69.674,8.5) 77.29,8.5 78.174,9.383 78.174,20.364 78.509,20.699 78.509,22.106 78.176,22.439 v1(78.176,23.331)
BUCK_LO_PWM: J2.52 R13.1 | length 79.5
  Power1 w0.254: R13.1@36.225,10.239 36.225,6.948 40.382,2.792 65.443,2.792 v1(72.409,9.758) ; v1(77.406,23.331) 77.406,35.732 77.923,36.25 J2.52@81.474,36.25
  Ground1 w0.254: v1(72.409,9.758) 77.202,9.758 77.561,10.117 77.561,16.983 77.174,17.371 77.174,21.85 77.406,22.082 v1(77.406,23.331)
DAC_EN: J2.75 R53.2 U11.7 | length 26.5
  Power1 w0.254: J2.75@84.874,49.05 87.898,49.05 90.674,51.826 v1(90.674,57) ; v1(91.174,60.086) 91.242,60.086 91.447,60.291 94.132,60.291 R53.2@94.174,60.25 ; R53.2@94.374,60.25 94.792,60.669 96.785,60.669 98.202,59.251 U11.7@101.601,59.251
  Power2 w0.254: v1(90.674,57) 91.174,57.5 v1(91.174,60.086)
FB: C49.1 R21.1 R35.2 U5.5 | length 4.9
  Power1 w0.254: R35.2@108.526,40.474 108.539,40.487 R21.1@108.539,41.713 ; R21.1@108.539,41.787 R21.1@108.539,41.713 ; v1(110.11,41.455) 108.87,41.455 108.799,41.527 108.724,41.527 R21.1@108.539,41.713
  Power2 w0.254: C49.1@108.217,41.753 108.339,41.875 U5.5@110.095,41.875
GND: C32.1 C33.1 C34.1 C35.1 C36.1 C37.1 C38.1 C39.1 C40.1 C41.1 C42.1 C43.1 C47.1 C48.1 C50.2 C51.2 C54.2 C55.1 C56.1 C57.1 C58.1 C59.1 C62.2 C63.2 C64.2 C65.2 C66.2 C67.2 C68.2 C70.2 C72.2 C73.2 C74.2 C75.2 C76.2 C77.1 C80.1 C83.1 C88.2 C89.2 C90.2 C91.2 C92.1 C93.1 C94.1 C95.1 C96.1 C97.1 C98.1 C99.2 C100.2 C101.2 C102.2 C103.2 C104.1 C105.2 C106.2 C107.1 C108.2 C109.1 C110.1 C111.1 C112.2 C113.2 C114.2 C115.2 D6.2 D8.2 D10.1 D11.2 D14.2 J2.7 J2.10 J2.19 J2.22 J2.29 J2.35 J2.38 J2.46 J2.47 J2.65 J2.83 J2.97 J2.111 J4.8 J5.1 L6.1 R1.1 R8.2 R9.2 R14.2 R15.2 R25.1 R33.1 R35.1 R43.1 R45.1 R52.1 R53.1 R54.1 R59.1 R60.1 R64.1 R65.1 R66.1 R67.1 T2.4 TP1.1 TP14.1 TP18.1 TP19.1 TP20.1 U2.15 U3.15 U4.2 U5.1 U5.9 U6.2 U6.4 U7.3 U7.5 U7.7 U7.8 U7.9 U7.10 U8.2 U8.5 U9.4 U10.2 U10.3 U11.1 U11.12 U11.29 U11.34 U11.35 U11.38 U11.39 U11.40 U11.41 U11.49@105.174,59.5 | length 165.5
  Power1 w0.254: C70.2@16.08,21.079 16.127,21.126 v1(16.127,21.66) ; C65.2@17.5,24.4 C66.2@18.686,24.4 ; v1(19.659,26.978) 19.662,26.982 20.747,26.982 U7.3@20.75,26.985 ; v1@30.758,14.573 30.741,14.556 30.741,14.25 31.269,13.722 C41.1@31.344,13.722 ; R15.2@34.313,10.719 R15.2@34.283,10.75 v1(34.283,10.233) 34.331,10.282 34.713,10.282 34.947,10.516 34.997,10.516 35.12,10.639 C35.1@35.12,10.689 C35.1@35.09,10.719 ; C33.1@38.779,10.841 38.779,10.795 39.005,10.569 39.135,10.569 v1(39.184,10.521) 39.358,10.695 39.358,10.91 39.416,10.968 R9.2@39.588,10.968 ; C36.1@40.396,39.981 C36.1@40.494,40.078 ; v1(43.596,43.097) 43.596,43.066 43.915,42.747 C34.1@43.965,42.747 ; C34.1@43.944,42.726 43.944,41.956 R14.2@43.923,41.935 43.931,41.928 44.421,41.928 v1(44.428,41.92) ; C32.1@43.965,46.86 43.965,47.546 43.89,47.621 R8.2@43.89,47.735 v1(44.409,47.735) ; v1(65.088,44.451) 65.972,44.451 C77.1@65.982,44.462 ; R25.1@66.174,25.018 66.174,25.118 v1(66.693,25.637) 66.801,25.745 67.351,25.745 U4.2@67.524,25.918 ; R43.1@67.711,41.464 67.856,41.609 68.532,41.609 ; v1(68.532,42.254) 68.532,41.609 ; U8.2@69.064,19.627 v1(69.064,18.252) U8.5@69.064,16.877 69.064,15.446 C67.2@69.137,15.373 ; C76.2@69.427,49.361 v1(69.977,49.361) 70.45,49.361 70.749,49.062 R45.1@70.749,49.012 71.762,49.012 C75.2@71.974,48.8 ; C73.2@69.479,41.49 69.36,41.609 68.532,41.609 ; U9.4@69.479,44.989 69.481,44.992 70.007,44.992 v1(70.01,44.994) ; v1(70.689,20.772) 70.713,20.796 71.475,20.796 C72.2@71.499,20.821 ; C74.2@72.379,42.345 72.388,42.354 73.077,42.354 v1(73.087,42.364) ; v1(72.664,56.046) 72.664,55.009 TP1.1@72.674,55 ; C68.2@73.164,15.326 73.189,15.301 v1(73.189,14.593) ; C112.2@77.534,37.665 77.597,37.729 77.711,37.729 78.134,38.152 78.431,38.152 v1(78.479,38.199) ; J2.10@81.474,19.45 82.712,19.45 83.512,18.65 J2.7@84.874,18.65 ; J2.22@81.474,24.25 81.597,24.373 82.109,24.373 82.802,25.066 v1(82.802,26.644) 82.802,27.301 82.951,27.45 J2.29@84.874,27.45 ; J2.38@81.474,30.65 82.774,30.65 v1(83.174,30.25) 83.574,29.85 J2.35@84.874,29.85 ; J2.46@81.474,33.85 82.835,33.85 v1(83.235,34.25) 83.635,34.65 J2.47@84.874,34.65 ; v1(83.767,63.327) 83.815,63.374 84.798,63.374 J2.111@84.874,63.45 ; v1(83.832,23.092) 83.901,23.092 84.135,23.327 84.751,23.327 J2.19@84.874,23.45 ; J2.65@84.874,45.05 84.919,45.095 87.238,45.095 v1(87.283,45.14) ; J2.83@84.874,52.25 84.9,52.276 87.283,52.276 v1(87.309,52.302) 87.309,52.308 87.52,52.519 87.52,57.518 87.336,57.702 v1(87.336,57.727) 84.997,57.727 J2.97@84.874,57.85 ; v1(91.674,38.5) TP14.1@91.674,39.5 ; C98.1@92.674,70.875 92.924,70.625 C98.1@93.197,70.352 ; R53.1@94.174,58.75 94.297,58.627 94.716,58.627 94.818,58.525 v1(94.887,58.525) 94.917,58.555 95.615,58.555 R54.1@95.645,58.585 ; v1(96.667,51.603) 96.667,52.343 C80.1@96.674,52.35 ; C101.2@96.924,68.7 C101.2@97.174,68.7 C101.2@97.231,68.643 ; C58.1@97.5,9.221 C57.1@97.5,11 ; C104.1@98.67,63.4 98.676,63.406 v1(99.42,63.406) 100.164,63.406 C105.2@100.17,63.412 100.361,63.412 100.677,63.096 100.789,63.096 v1(100.837,63.048) 100.837,63.02 101.608,62.25 U11.1@101.774,62.25 102.424,62.25 v1(104.489,60.185) U11.49@105.174,59.5 v1(104.489,58.815) 102.424,56.75 U11.12@101.774,56.75 101.608,56.75 100.896,56.038 C102.2@100.045,56.038 ; R60.1@98.924,68.643 v1(98.924,67.834) 98.924,67.025 C96.1@99.174,66.775 ; v1@99.053,74.854 99.099,74.854 v1(99.174,74.929) 99.483,75.238 C88.2@99.674,75.238 ; C100.2@102.174,66.762 102.285,66.762 102.412,66.889 v1(102.412,67.695) R52.1@102.412,68.5 ; C83.1@105.174,48.85 105.236,48.787 106.611,48.787 C92.1@106.674,48.725 ; U11.41@105.924,62.9 105.924,62.325 106.057,62.191 106.625,62.191 v1(106.674,62.143) 106.722,62.191 107.29,62.191 107.424,62.325 U11.38@107.424,62.9 ; C93.1@106.674,51.85 106.68,51.844 v1(106.68,51.273) ; v1(106.974,58.815) 107.031,58.757 v1(107.879,58.757) ; v1(107.732,61.411) 108.077,61.756 108.567,61.756 U11.35@108.574,61.75 ; v1@107.886,58.75 U11.29@108.574,58.75 ; 107.961,61.25 U11.34@108.574,61.25 ; D10.1@109.674,73.485 110.174,72.985 110.174,72.691 v1@110.134,72.652 ; C95.1@110.174,60.15 110.236,60.213 111.611,60.213 C94.1@111.674,60.275 111.688,60.275 111.936,60.523 C103.2@111.936,62 ; v1(110.174,72.652) 110.174,70.5 D11.2@110.674,70 D11.2@110.902,69.772 ; v1@110.598,39.65 v1(110.7,39.65) ; C89.2@111.174,51.738 v1(111.924,51.738) C90.2@112.674,51.738 ; L6.1@112.871,69.772 113.444,69.199 L6.1@113.444,69 ; R59.1@116.674,64.238 v1(117.424,64.238) C91.2@118.174,64.238 ; C107.1@122.163,18.238 122.168,18.233 122.168,16.905 v1(122.174,16.9)
  Power1 w0.4: C41.1@31.344,13.722 C40.1@32.551,13.722 ; v1(39.87,39.99) 39.899,39.99 39.92,40.011 40.367,40.011 C36.1@40.396,39.981 ; C37.1@40.477,41.218 40.477,41.143 40.261,40.927 40.261,40.711 v1(40.24,40.69) 40.261,40.669 40.261,40.386 40.494,40.153 C36.1@40.494,40.078 ; C106.2@92.674,50.3 v1(92.674,49.4) 92.674,48.5 TP20.1@93.174,48 ; C96.1@99.174,66.75 99.174,66.775 99.349,66.95 v1@99.698,66.95 ; v1@99.699,66.951 99.86,66.951 v1(99.881,66.971) 99.901,66.951 100.149,66.951 ; 100.149,66.95 100.499,66.95 100.674,66.775 C97.1@100.674,66.75 100.686,66.762 C100.2@102.174,66.762 ; C100.2@102.285,66.762 C99.2@103.674,66.762 ; R35.1@108.526,39.274 110.222,39.274 v1@110.598,39.65 ; D11.2@110.902,69.772 L6.1@112.871,69.772 ; TP19.1@118.674,55 v1(118.674,56.25) D14.2@118.674,58
  Power1 w0.6: C101.2@97.231,68.643 97.422,68.452 v1(98.311,68.452) ; v1@98.322,68.463 98.743,68.463 R60.1@98.924,68.643
  Power1 w0.8: C98.1@92.924,70.625 v1(94.999,70.625) C101.2@96.924,68.7
  Power2 w0.254: R65.1@30.718,15.339 30.736,15.321 30.736,14.411 v1(30.753,14.394) ; R65.1@30.727,15.347 R67.1@30.727,16.235 ; v1(33.437,10.984) 33.437,11.026 33.763,11.351 C42.1@33.813,11.351 C43.1@34.476,11.351 C43.1@34.519,11.351 ; v1(34.587,13.956) 34.611,13.98 34.611,14.562 U3.15@34.613,14.564 ; R66.1@38.164,39.956 R66.1@38.169,39.96 ; R64.1@39.062,39.96 R64.1@39.066,39.965 R64.1@39.079,39.978 ; U2.15@39.728,43.56 39.73,43.558 40.315,43.558 v1(40.355,43.518) ; v1@39.857,39.978 v1(39.87,39.99) ; C38.1@43.107,43.195 43.107,43.19 43.152,43.145 43.548,43.145 v1(43.596,43.097) ; R1.1@65.755,35.419 R1.1@65.782,35.446 ; v1(77.364,47.708) 77.391,47.681 77.391,47.215 C109.1@77.419,47.188 ; C110.1@78.476,37.718 78.477,37.72 v1(78.479,38.199) v1(78.479,38.199) ; C108.2@90.374,23.75 v1(90.374,24.65) ; v1(91.674,38.5) 91.674,38.484 92.382,37.775 C64.2@92.382,37.75 v1(93.238,37.75) 93.852,37.136 94.208,37.136 U6.2@94.381,36.963 ; v1(105.859,61.3) 105.859,61.314 106.674,62.129 v1(106.674,62.143) ; v1(106.974,58.815) 107.002,58.786 107.85,58.786 v1(107.879,58.757) ; v1(106.974,60.185) 107.021,60.232 107.021,60.7 v1(107.732,61.411) ; C55.1@107.275,33.422 C55.1@107.375,33.322 ; R33.1@108.562,37.627 109.652,37.627 111.025,39 U5.9@112,39 112.557,39 U5.9@113.905,37.652 ; C114.2@111.484,46.773 C114.2@111.5,46.789 ; U5.1@113.905,35.275 U5.1@113.905,36.125 ; U10.2@121.539,16.9 v1(122.174,16.9) U10.3@122.809,16.9
  Power2 w0.35: C39.1@43.107,42.495 C38.1@43.107,43.19
  Power2 w0.4: R66.1@38.169,39.96 R64.1@39.062,39.96 ; R64.1@39.079,39.978 v1@39.857,39.978 ; R1.1@65.782,35.446 v1(66.566,35.446) ; U5.1@113.905,35.275 114.052,35.128 C111.1@114.052,34.157
  Power2 w0.6: C55.1@107.275,33.422 v1(107.275,34.672) ; C114.2@111.5,46.789 v1(111.5,47.757) C113.2@111.5,48.773 ; U5.1@113.905,36.125 U5.9@113.905,37.652 ; v1(119.888,52.427) C115.2@121.017,52.427
  Power2 w0.8: C56.1@115.147,32.22 115.147,32.658 115.297,32.808 v1(116.154,32.808)
  other v1: 96.644,9.186 97.365,10.117 69.066,16.014 20.826,18.696 83.112,19.05 21.949,19.337 20.802,20.01 18.077,24.41 72.674,26 74.174,26 72.174,31.5 73.735,37.514 74.599,37.546 110.7,38.35 112,38.35 113.3,38.35 101.462,38.4 98.109,38.813 98.977,38.815 112,39.65 113.3,39.65 105.908,48.787 71.323,49.014 101.056,56.2 104.489,57.7 105.859,57.7 103.374,58.815 105.859,58.815 103.374,60.185 105.859,60.185 110.892,60.224 111.942,61.114 104.489,61.3 112.204,69.758 102.174,79.143
Input_I: C72.1 J2.14 R32.2 TP17.1 | length 12.9
  Power1 w0.254: R32.2@72.703,19.432 72.703,20.817 C72.1@72.699,20.821 72.867,20.653 77.925,20.653 78.321,21.05 J2.14@81.474,21.05 ; R32.2@72.769,19.425 72.923,19.271 73.955,19.271 TP17.1@74.853,18.374
Input_V: C74.1 J2.12 R42.2 | length 32.4
  Power1 w0.254: R42.2@71.054,43.787 71.054,42.47 C74.1@71.179,42.345 71.179,41.505 71.664,41.019 75.654,41.019 76.517,40.156 76.517,21.66 76.868,21.309 v1(77.755,21.309) ; v1(78.991,20.055) 79.059,20.055 79.131,20.127 81.351,20.127 J2.12@81.474,20.25
  Power2 w0.254: v1(77.755,21.309) 77.755,21.3 78.991,20.064 v1(78.991,20.055)
INT: J2.85 R55.2 U11.9 | length 24.6
  Power1 w0.254: J2.85@84.874,53.05 86.935,53.05 v1(86.939,53.045) ; v1(88.647,55.584) 88.669,55.606 88.669,57.525 88.817,57.673 92.096,57.673 R55.2@92.16,57.737 92.35,57.737 92.477,57.61 92.477,57.42 93.174,56.723 93.174,55.211 93.322,55.062 96.444,55.062 96.674,55.292 96.674,56.506 98.417,58.25 U11.9@101.774,58.25
  Ground1 w0.254: v1(86.939,53.045) 87.006,53.045 88.647,54.686 v1(88.647,55.584)
ISO1_5V: C31.1 C44.2 C79.1 D2.1 D4.1 pad.2 R3.1 R16.2 | length 53.2
  Power1 w0.254: D2.1@41.194,15.304 D2.1@41.346,15.304 ; D4.1@55.536,33.365 D4.1@55.536,33.518
  Power1 w0.4: v1(39.986,14.374) 40.007,14.394 40.131,14.394 41.041,15.304 D2.1@41.194,15.304
  Power1 w0.6: D2.1@41.346,15.304 43.747,12.904 43.747,12.58 43.747,8.88 44.102,8.524 55.145,8.524 58.72,12.099 58.72,13.033 60.876,15.19 v1(60.876,16.828) ; D4.1@55.536,33.365 55.536,31.357 54.674,30.494 54.674,28.5 60.818,22.355 v1(60.836,22.355)
  Ground1 w0.6: v1(60.836,22.355) v1@60.856,22.335
  Power2 w0.4: C79.1@39.208,13.569 C31.1@39.208,14.364 ; C31.1@39.252,14.502 39.394,14.644 R3.1@39.394,15.267 ; C31.1@39.39,14.364 39.976,14.364 v1(39.986,14.374)
  Power2 w0.6: v1@60.856,22.335 60.856,16.848 v1(60.876,16.828)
